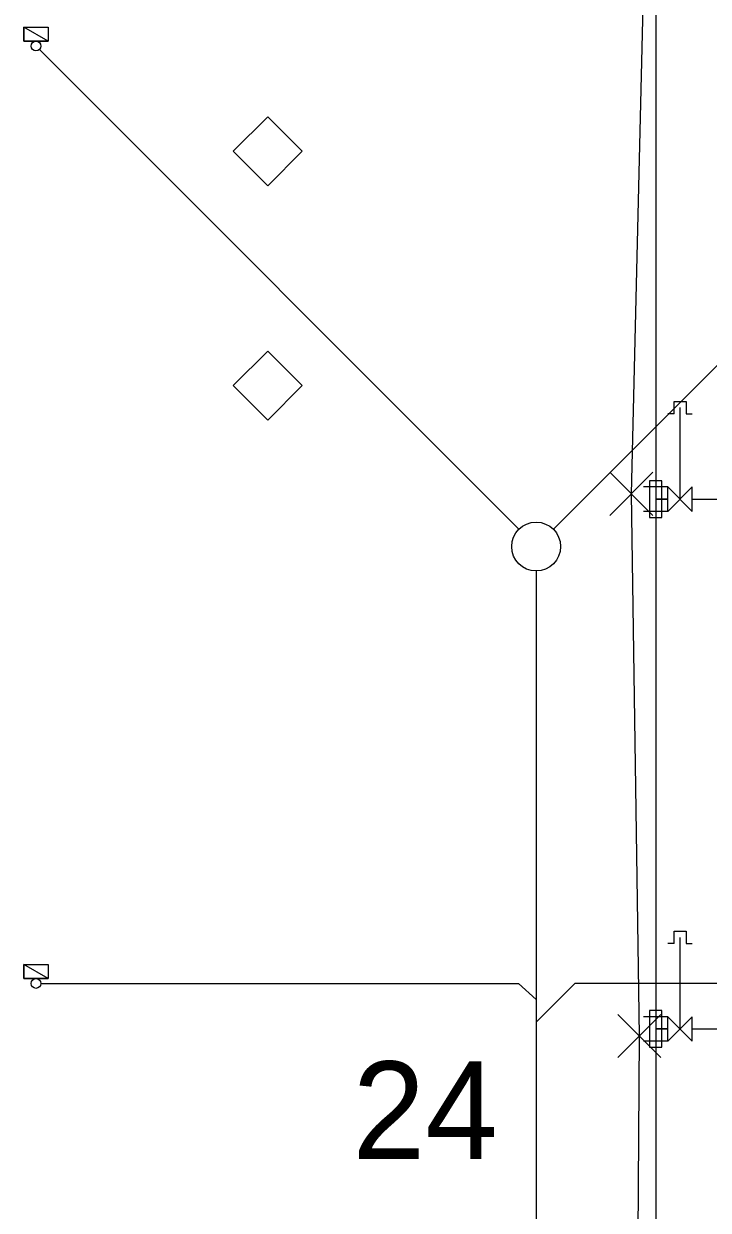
# Model space of a CAD drawing. Extents: x -263964 to -263544, y -1242317 to -1242020.
# Drawn here: x -263937.09 to -263923.07, y -1242121 to -1242096.69 of the extents above; entities that cross this region are included whole.
import ezdxf

# ---------------------------------------------------------------- set-up
doc = ezdxf.new("R2010")
doc.units = 0
for name, color, linetype in [('KFA_KOORDINACNA_SITUACIA_DSP_SEDA', 7, 'Continuous'), ('KFA_SO_50-2_POZIARNY_VODOVOD_BODY', 7, 'Continuous'), ('KFA_SO_50-2_POZIARNY_VODOVOD_TRASA', 7, 'Continuous')]:
    doc.layers.add(name, color=color, linetype=linetype)

msp = doc.modelspace()

# ---------------------------------------------------------------- linework, layer by layer
at = {"layer": 'KFA_KOORDINACNA_SITUACIA_DSP_SEDA'}
for p, q in [((-263924.143, -1242082.64), (-263924.143, -1242185.14)), ((-263937.093, -1242097.052), (-263937.093, -1242096.762)), ((-263937.093, -1242096.762), (-263936.593, -1242096.762)), ((-263936.593, -1242097.052), (-263937.093, -1242096.762)), ((-263936.593, -1242097.052), (-263937.093, -1242096.762)), ((-263937.093, -1242096.762), (-263937.093, -1242097.052)), ((-263936.593, -1242096.762), (-263936.593, -1242097.052)), ((-263936.593, -1242097.052), (-263937.093, -1242097.052)), ((-263937.093, -1242097.052), (-263936.593, -1242097.052)), ((-263936.772, -1242097.223), (-263926.946, -1242107.049)), ((-263916.414, -1242097.223), (-263926.239, -1242107.049)), ((-263932.8, -1242099.307), (-263932.093, -1242098.6)), ((-263932.093, -1242098.6), (-263931.386, -1242099.307)), ((-263932.093, -1242098.6), (-263932.093, -1242098.6)), ((-263932.093, -1242100.014), (-263932.8, -1242099.307)), ((-263931.386, -1242099.307), (-263932.093, -1242100.014)), ((-263932.8, -1242104.107), (-263932.093, -1242103.4)), ((-263932.093, -1242103.4), (-263931.386, -1242104.107)), ((-263932.093, -1242103.4), (-263932.093, -1242103.4)), ((-263932.093, -1242104.814), (-263932.8, -1242104.107)), ((-263931.386, -1242104.107), (-263932.093, -1242104.814)), ((-263923.768, -1242104.682), (-263923.768, -1242104.432)), ((-263923.768, -1242104.432), (-263923.518, -1242104.432)), ((-263923.518, -1242104.432), (-263923.518, -1242104.682)), ((-263923.768, -1242104.682), (-263923.893, -1242104.682)), ((-263923.643, -1242106.432), (-263923.643, -1242104.557)), ((-263923.518, -1242104.682), (-263923.393, -1242104.682)), ((-263923.893, -1242106.182), (-263924.393, -1242106.182)), ((-263924.018, -1242106.057), (-263924.268, -1242106.057)), ((-263924.268, -1242106.057), (-263924.268, -1242106.807)), ((-263924.018, -1242106.807), (-263924.018, -1242106.057)), ((-263923.893, -1242106.682), (-263923.893, -1242106.182)), ((-263923.893, -1242106.182), (-263923.393, -1242106.682)), ((-263923.393, -1242106.182), (-263923.893, -1242106.682)), ((-263923.393, -1242106.682), (-263923.393, -1242106.182)), ((-263924.143, -1242106.432), (-263923.893, -1242106.432)), ((-263923.893, -1242106.432), (-263924.143, -1242106.432)), ((-263923.393, -1242106.432), (-263903.343, -1242106.432)), ((-263923.893, -1242106.682), (-263924.393, -1242106.682)), ((-263924.268, -1242106.807), (-263924.018, -1242106.807)), ((-263926.593, -1242107.902), (-263926.593, -1242154.252)), ((-263926.593, -1242107.902), (-263926.593, -1242154.252)), ((-263923.768, -1242115.532), (-263923.768, -1242115.282)), ((-263923.768, -1242115.282), (-263923.518, -1242115.282)), ((-263923.643, -1242117.282), (-263923.643, -1242115.407)), ((-263923.518, -1242115.282), (-263923.518, -1242115.532)), ((-263923.768, -1242115.532), (-263923.893, -1242115.532)), ((-263923.518, -1242115.532), (-263923.393, -1242115.532)), ((-263937.093, -1242116.252), (-263937.093, -1242115.962)), ((-263937.093, -1242115.962), (-263936.593, -1242115.962)), ((-263936.593, -1242116.252), (-263937.093, -1242115.962)), ((-263936.593, -1242116.252), (-263937.093, -1242115.962)), ((-263937.093, -1242115.962), (-263937.093, -1242116.252)), ((-263936.593, -1242115.962), (-263936.593, -1242116.252)), ((-263936.593, -1242116.252), (-263937.093, -1242116.252)), ((-263937.093, -1242116.252), (-263936.593, -1242116.252)), ((-263936.743, -1242116.352), (-263926.953, -1242116.352)), ((-263926.953, -1242116.352), (-263926.592, -1242116.677)), ((-263925.797, -1242116.352), (-263926.592, -1242117.147)), ((-263916.443, -1242116.352), (-263925.797, -1242116.352)), ((-263923.893, -1242117.032), (-263924.393, -1242117.032)), ((-263924.018, -1242116.907), (-263924.268, -1242116.907)), ((-263924.268, -1242116.907), (-263924.268, -1242117.657)), ((-263924.018, -1242117.657), (-263924.018, -1242116.907)), ((-263923.893, -1242117.532), (-263923.893, -1242117.032)), ((-263923.893, -1242117.032), (-263923.393, -1242117.532)), ((-263923.393, -1242117.032), (-263923.893, -1242117.532)), ((-263923.393, -1242117.532), (-263923.393, -1242117.032)), ((-263924.143, -1242117.282), (-263923.893, -1242117.282)), ((-263923.893, -1242117.282), (-263924.143, -1242117.282)), ((-263923.393, -1242117.282), (-263906.493, -1242117.282)), ((-263923.893, -1242117.532), (-263924.393, -1242117.532)), ((-263924.268, -1242117.657), (-263924.018, -1242117.657))]:
    msp.add_line(p, q, dxfattribs=at)
for centre, radius in [((-263936.843, -1242097.152), 0.1), ((-263926.593, -1242107.402), 0.5), ((-263936.843, -1242116.352), 0.1)]:
    msp.add_circle(centre, radius, dxfattribs=at)
at = {"layer": 'KFA_SO_50-2_POZIARNY_VODOVOD_BODY'}
for p, q in [((-263925.086, -1242106.764), (-263924.202, -1242105.88)), ((-263924.202, -1242106.764), (-263925.086, -1242105.88)), ((-263924.644, -1242106.322), (-263924.644, -1242106.322)), ((-263924.921, -1242117.869), (-263924.037, -1242116.985)), ((-263924.037, -1242117.869), (-263924.921, -1242116.985)), ((-263924.479, -1242117.427), (-263924.479, -1242117.427))]:
    msp.add_line(p, q, dxfattribs=at)
at = {"layer": 'KFA_SO_50-2_POZIARNY_VODOVOD_TRASA'}
msp.add_lwpolyline([(-263924.931, -1242185.127), (-263924.146, -1242197.091), (-263924.296, -1242220.899), (-263924.1, -1242250.121), (-263913.986, -1242249.798), (-263886.91, -1242249.876), (-263867.714, -1242249.83), (-263837.257, -1242249.836), (-263828.162, -1242249.901), (-263787.99, -1242250.032), (-263788.202, -1242220.837), (-263788.195, -1242200.509), (-263788.092, -1242179.915), (-263788.062, -1242148.958), (-263787.919, -1242127.952), (-263787.952, -1242110.966), (-263788.129, -1242082.536), (-263828.429, -1242082.723), (-263836.783, -1242082.559), (-263867.306, -1242082.615), (-263886.71, -1242082.472), (-263924.08, -1242082.613), (-263924.644, -1242106.322), (-263924.479, -1242117.427)], close=True, dxfattribs=at)

# ---------------------------------------------------------------- texts
at = {"layer": 'KFA_SO_50-2_POZIARNY_VODOVOD_BODY'}
msp.add_text('24', height=2, dxfattribs=at).set_placement((-263930.354, -1242119.948))

doc.saveas('drawing.dxf')
